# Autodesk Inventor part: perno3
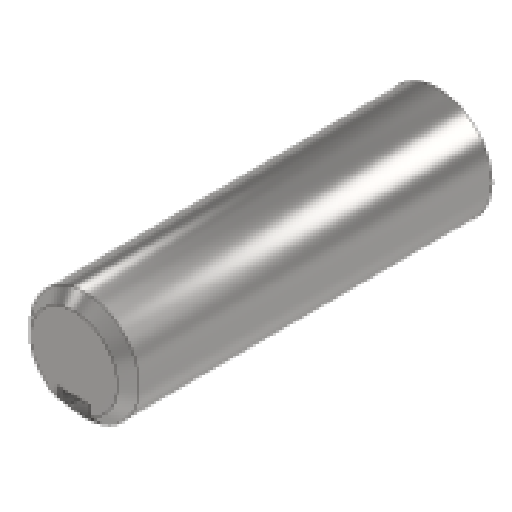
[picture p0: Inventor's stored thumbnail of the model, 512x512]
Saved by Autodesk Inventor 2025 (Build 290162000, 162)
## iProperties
Created: 2025-10
Part Number: perno3
Material: Acciaio inossidabile
Document SubType Name: Modeling
Designer: Ryzen5700u
Density: 8 g/cm^3
Appearance: Semilucidato
Mass: 167.451 g
Surface Area: 47.5924 cm^2
Volume: 20.9314 cm^3
Author: Ryzen5700u
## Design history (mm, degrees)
node "Piano di lavoro1"
sketch "Schizzo1"
  geometry: C1 r 10 at (0, 0); 1 further point
  constraints: 1 centre point, 1 coincident
  dimensions: "d0" = 20 diameter of C1
extrude "Estrusione1" new body sketch "Schizzo1" distance "d1" = 67; taper "d2" = 0 deg
chamfer "Smusso1" distance "d3" = 2; stored, may be unused: second distance "d4" = 2, angle "d5" = 45 deg
sketch "Schizzo2"
  geometry: L1 (3, -12.5)-(-3, -12.5) reference; L2 (3, -9.539)-(3, -12.5) reference; L3 (-3, -12.5)-(-3, -9.539) reference; L4 (3, -9.539)-(-3, -9.539); L5 (-3, -9.539)-(-3, -5.539); L6 (-3, -5.539)-(3, -5.539); L7 (3, -5.539)-(3, -9.539); A1 r 10 centre (0, 0) between (3, -9.539) and (-3, -9.539) reference; 2 further points
  constraints: 8 end point, 2 parallel, 1 horizontal, 1 perpendicular
  dimensions: "d6" = 4 distance of L4.end L5.end
extrude "Estrusione2" cut sketch "Schizzo2" distance "d7" = 50; taper "d8" = 0 deg
node "Solido1"
node "Riferimento1"
node "Riferimento2"
node "Riferimento3"
